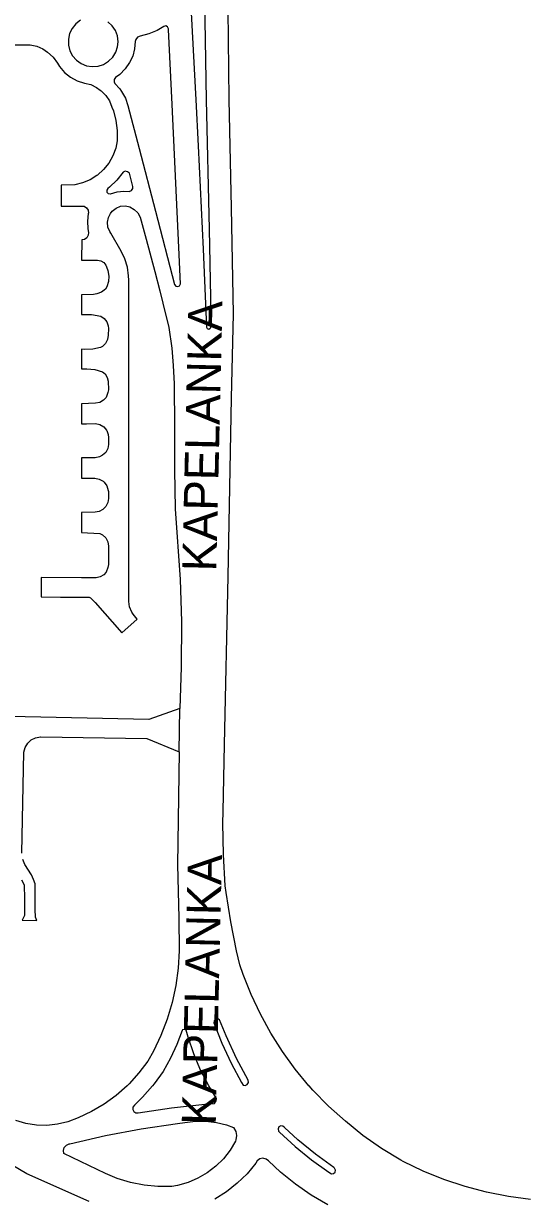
# Model space of a CAD drawing. Extents: x -304109 to -273954, y 21500 to 39796.
# Drawn here: x -294638.1 to -294489.1, y 28427.2 to 28772.6 of the extents above; entities that cross this region are included whole.
import ezdxf

# ---------------------------------------------------------------- set-up
doc = ezdxf.new("R2010")
doc.units = 0
doc.layers.add('krawedzie_ulic', color=7, linetype='Continuous')
doc.layers.add('nazwy_ulic', color=7, linetype='Continuous')

msp = doc.modelspace()

# ---------------------------------------------------------------- linework, layer by layer
at = {"layer": 'krawedzie_ulic'}
for points in [[(-294584.373, 28750.14), (-294583.568, 28712.137), (-294583.142, 28692.054), (-294583.142, 28683.142), (-294583.233, 28682.877), (-294583.62, 28682.645), (-294584.048, 28682.791), (-294584.211, 28683.213), (-294585.209, 28706.243), (-294586.706, 28736.585), (-294587.346, 28750.11), (-294589.288, 28786.733)], [(-294585.015, 28785.266), (-294584.373, 28750.14)], [(-294489.091, 28426.892), (-294495.579, 28427.789), (-294502.001, 28429.081), (-294508.333, 28430.762), (-294514.549, 28432.826), (-294520.629, 28435.266), (-294526.548, 28438.072), (-294527.25, 28438.435), (-294532.898, 28441.928), (-294538.325, 28445.755), (-294543.512, 28449.901), (-294548.441, 28454.352), (-294553.092, 28459.092), (-294554.172, 28460.278), (-294554.22, 28460.333), (-294558.274, 28465.245), (-294562.011, 28470.402), (-294565.418, 28475.783), (-294568.48, 28481.367), (-294571.185, 28487.133), (-294573.523, 28493.057), (-294574.481, 28495.853), (-294575.482, 28500), (-294577.211, 28508.554), (-294578.546, 28517.177), (-294578.795, 28519.151), (-294579.346, 28528.309), (-294579.498, 28537.482), (-294579.452, 28540.927), (-294578.991, 28560.669), (-294577.915, 28609.987), (-294576.966, 28662.456), (-294576.367, 28687.225), (-294577.01, 28718.357), (-294577.654, 28750.174), (-294578.099, 28785.592)], [(-294621.367, 28773.49), (-294622.726, 28772.454), (-294623.808, 28771.132), (-294624.553, 28769.595), (-294624.923, 28767.927), (-294624.895, 28766.219), (-294624.473, 28764.564), (-294623.678, 28763.052), (-294622.555, 28761.765), (-294621.164, 28760.774), (-294619.581, 28760.132), (-294617.892, 28759.875), (-294616.189, 28760.015), (-294614.566, 28760.547), (-294613.11, 28761.44), (-294611.901, 28762.647), (-294611.004, 28764.101), (-294610.469, 28765.723), (-294610.32, 28767.19)], [(-294610.32, 28767.19), (-294610.52, 28768.887), (-294611.107, 28770.491), (-294612.05, 28771.915), (-294613.297, 28773.082)], [(-294603.77, 28768.86), (-294604.56, 28768.51), (-294605.112, 28767.845), (-294605.29, 28767.28), (-294605.46, 28765.102), (-294606.023, 28762.991), (-294606.93, 28761.07), (-294608.227, 28759.2), (-294609.831, 28757.585), (-294611.04, 28756.68), (-294611.445, 28756.104), (-294611.479, 28755.4), (-294611.28, 28754.96), (-294609.82, 28753.33), (-294609.283, 28752.597), (-294608.159, 28750.596), (-294607.4, 28748.43), (-294604.09, 28735.79), (-294599.3, 28717.36), (-294593.73, 28695.859), (-294593.727, 28695.851), (-294593.366, 28695.38), (-294592.791, 28695.234), (-294592.248, 28695.476), (-294591.972, 28696.001), (-294592.494, 28706.721), (-294594.44, 28748.709), (-294595.529, 28770.787), (-294595.527, 28771.01), (-294595.785, 28771.553), (-294596.321, 28771.824), (-294596.911, 28771.709), (-294598.851, 28770.527), (-294601.246, 28769.504), (-294603.77, 28768.86)], [(-294644.8, 28766.29), (-294636.11, 28766.31), (-294634.202, 28765.902), (-294632.417, 28765.115), (-294631.05, 28764.17), (-294629.438, 28762.679), (-294628.122, 28760.921), (-294627.55, 28759.88), (-294626.066, 28758.194), (-294624.307, 28756.798), (-294622.328, 28755.735), (-294620.193, 28755.04), (-294620.15, 28755.03), (-294618.35, 28754.584), (-294616.686, 28753.763), (-294615.57, 28752.92), (-294615.302, 28752.718), (-294613.914, 28751.38), (-294612.831, 28749.784), (-294612.1, 28748), (-294611.695, 28746.899), (-294610.932, 28744.021), (-294610.562, 28741.067), (-294610.59, 28738.09), (-294611.013, 28735.949), (-294611.85, 28733.655), (-294613.05, 28731.529), (-294614.58, 28729.627), (-294616.4, 28728), (-294616.55, 28727.884), (-294618.549, 28726.614), (-294620.733, 28725.697), (-294623.04, 28725.16), (-294627.03, 28725.02), (-294627.05, 28718.9), (-294621.17, 28718.91), (-294620.319, 28718.856), (-294619.584, 28718.424), (-294619.122, 28717.708), (-294619.032, 28716.86), (-294619.06, 28716.7), (-294619.343, 28714.437), (-294619.227, 28712.16), (-294619.05, 28711.17)], [(-294606.96, 28728.53), (-294607.502, 28729.007), (-294608.213, 28729.13), (-294608.86, 28728.88), (-294610.719, 28726.538), (-294612.873, 28724.464), (-294613.33, 28724.09), (-294613.655, 28723.593), (-294613.603, 28723.002), (-294613.195, 28722.57), (-294612.608, 28722.483), (-294612.5, 28722.51), (-294610.578, 28723.087), (-294608.58, 28723.271), (-294607.03, 28723.14), (-294606.392, 28723.474), (-294606.023, 28724.093), (-294605.99, 28724.61), (-294606.96, 28728.53)], [(-294607.15, 28602.69), (-294607.18, 28627.96), (-294607.15, 28671.928), (-294607.18, 28697.08), (-294607.204, 28698.371), (-294607.552, 28700.912), (-294608.29, 28703.368), (-294609.4, 28705.68), (-294612.42, 28710.92), (-294612.764, 28711.434), (-294613.288, 28712.73), (-294613.426, 28714.121), (-294613.166, 28715.495), (-294612.53, 28716.74), (-294612.003, 28717.389), (-294610.879, 28718.277), (-294609.554, 28718.821), (-294608.13, 28718.98), (-294606.844, 28718.643), (-294605.557, 28717.917), (-294604.51, 28716.874), (-294603.78, 28715.59), (-294602.02, 28709.17), (-294599.503, 28699.713), (-294598.077, 28693.963), (-294597.112, 28690.364), (-294595.376, 28683.162), (-294594.52, 28677.126), (-294594.093, 28672.041), (-294593.808, 28666.624), (-294593.713, 28653.792), (-294593.744, 28641.376), (-294593.527, 28629.896), (-294592.037, 28609.148), (-294591.704, 28596.823), (-294591.796, 28583.358), (-294592.126, 28571.239)], [(-294619.05, 28711.17), (-294619.085, 28710.32), (-294619.5, 28709.577), (-294620.206, 28709.101), (-294621.01, 28708.99), (-294621.04, 28702.95), (-294616.34, 28702.96)], [(-294616.34, 28702.96), (-294615.342, 28702.814), (-294614.477, 28702.294), (-294613.879, 28701.482), (-294613.72, 28701.04), (-294613.37, 28699.92), (-294613.056, 28698.332), (-294613.138, 28696.715), (-294613.614, 28695.167), (-294613.96, 28694.5), (-294615.16, 28693.61), (-294616.553, 28693.068), (-294617.56, 28692.92), (-294621.07, 28692.82), (-294621.06, 28687.06), (-294618.092, 28686.983), (-294615.39, 28686.56), (-294614.361, 28685.864), (-294613.604, 28684.878), (-294613.197, 28683.704), (-294613.14, 28682.93), (-294613.18, 28680.92), (-294613.382, 28679.672), (-294613.962, 28678.548), (-294614.862, 28677.659), (-294615.45, 28677.31), (-294617.746, 28676.827), (-294620.09, 28676.74), (-294621.05, 28676.82), (-294621.07, 28671.04), (-294619.46, 28671.101), (-294617.137, 28670.851), (-294614.89, 28670.21), (-294614.105, 28669.554), (-294613.484, 28668.557), (-294613.23, 28667.41), (-294613.16, 28664.88), (-294613.291, 28664.12), (-294613.84, 28662.68), (-294614.628, 28661.817), (-294615.704, 28661.202), (-294616.92, 28660.96), (-294621.066, 28660.768), (-294621.064, 28654.868), (-294619.64, 28654.91), (-294616.93, 28654.99), (-294615.662, 28654.681), (-294614.547, 28654.004), (-294613.687, 28653.023), (-294613.66, 28652.98), (-294613.201, 28651.796), (-294613.11, 28650.84), (-294613.13, 28648.83), (-294613.356, 28647.601), (-294613.957, 28646.504), (-294614.871, 28645.652), (-294615.81, 28645.19), (-294617.008, 28644.909), (-294617.55, 28644.91), (-294621.06, 28644.93), (-294621.05, 28638.904), (-294620.05, 28638.9), (-294617.152, 28638.88), (-294615.85, 28638.627), (-294614.681, 28638), (-294614.41, 28637.78), (-294613.615, 28636.638), (-294613.176, 28635.317), (-294613.13, 28635), (-294613.16, 28632.98), (-294613.337, 28631.736), (-294613.894, 28630.61), (-294614.775, 28629.713), (-294615.892, 28629.137), (-294617.03, 28628.94), (-294621.07, 28628.85), (-294621.07, 28622.96), (-294615.64, 28622.66), (-294614.867, 28622.234), (-294613.942, 28621.343), (-294613.333, 28620.213), (-294613.1, 28618.95), (-294613.15, 28613.53), (-294613.298, 28612.645), (-294613.85, 28611.26), (-294614.491, 28610.547), (-294615.549, 28609.89), (-294616.76, 28609.6), (-294621.06, 28609.65), (-294632.93, 28609.69), (-294632.95, 28604), (-294627.2, 28603.97), (-294618.81, 28603.98), (-294618.459, 28603.794), (-294617.05, 28602.42)], [(-294617.05, 28602.42), (-294609.21, 28593.44), (-294604.69, 28597.49), (-294605.91, 28598.97), (-294606.291, 28599.568), (-294606.912, 28601.076), (-294607.15, 28602.69)], [(-294592.126, 28571.239), (-294601.281, 28568.04), (-294642.084, 28568.91)], [(-294592.335, 28558.511), (-294592.126, 28571.239)], [(-294638.6, 28528.738), (-294637.985, 28558.415), (-294637.612, 28559.791), (-294636.873, 28561.01), (-294635.826, 28561.978), (-294634.552, 28562.618), (-294633.151, 28562.881), (-294632.977, 28562.886), (-294601.815, 28562.425), (-294592.335, 28558.511)], [(-294592.335, 28558.511), (-294592.849, 28525.251), (-294592.496, 28509.676), (-294592.33, 28500), (-294592.621, 28494.886), (-294593.31, 28489.81), (-294594.393, 28484.804), (-294595.863, 28479.897), (-294597.712, 28475.119), (-294599.927, 28470.501), (-294601.577, 28467.565), (-294604.169, 28464.12), (-294607.068, 28460.931), (-294607.676, 28460.333), (-294610.911, 28457.484), (-294614.396, 28454.948), (-294618.102, 28452.745), (-294621.995, 28450.895), (-294625.081, 28449.728), (-294628.112, 28449.009), (-294631.21, 28448.684), (-294634.325, 28448.758), (-294637.404, 28449.23), (-294640.397, 28450.092)], [(-294638.704, 28520.907), (-294637.938, 28519.445), (-294637.859, 28515.314), (-294637.819, 28510.356), (-294638.469, 28509.027), (-294634.203, 28508.902), (-294634.573, 28509.896), (-294634.667, 28512.141), (-294634.707, 28515.554), (-294634.668, 28518.235), (-294634.708, 28519.711), (-294635.158, 28520.966), (-294635.727, 28522.329), (-294637.674, 28525.423), (-294638.335, 28526.812)], [(-294582.157, 28478.841), (-294579.811, 28472.838), (-294577.098, 28466.993), (-294574.027, 28461.327), (-294573.566, 28460.544), (-294572.916, 28460.461), (-294572.334, 28460.762), (-294572.026, 28461.342), (-294572.093, 28461.968), (-294575.497, 28468.405), (-294578.543, 28475.019), (-294580.453, 28479.732), (-294581.015, 28480.011), (-294581.634, 28479.905), (-294582.07, 28479.453), (-294582.157, 28478.841)], [(-294605.52, 28454.648), (-294605.942, 28454.088), (-294605.997, 28453.388), (-294605.668, 28452.769), (-294605.058, 28452.422), (-294604.421, 28452.437), (-294594.639, 28453.889), (-294584.806, 28454.945), (-294581.979, 28455.174), (-294581.508, 28455.901), (-294581.397, 28456.623), (-294583.67, 28460.333), (-294586.053, 28464.926), (-294588.075, 28469.69), (-294589.722, 28474.596), (-294590.296, 28476.674), (-294590.816, 28476.902), (-294591.36, 28476.743), (-294591.492, 28476.623), (-294592.999, 28472.443), (-294594.876, 28468.415), (-294597.107, 28464.573), (-294599.674, 28460.946), (-294600.159, 28460.333), (-294603.095, 28456.998), (-294605.52, 28454.648)], [(-294575.771, 28444.094), (-294577.393, 28441.378), (-294579.345, 28438.888), (-294581.595, 28436.665), (-294584.107, 28434.742), (-294586.842, 28433.152), (-294589.755, 28431.919), (-294592.8, 28431.063), (-294594.5, 28430.76), (-294598.595, 28430.759), (-294602.671, 28431.158), (-294606.688, 28431.952), (-294610.608, 28433.134), (-294614.054, 28434.534), (-294626.283, 28440.397), (-294626.4, 28441.325), (-294626.123, 28442.219), (-294625.502, 28442.918), (-294624.647, 28443.298), (-294624.508, 28443.322), (-294614.043, 28445.688), (-294603.497, 28447.662), (-294592.885, 28449.242), (-294590.646, 28449.524), (-294587.585, 28449.947), (-294584.495, 28449.971), (-294581.427, 28449.596), (-294578.434, 28448.829), (-294576.339, 28448.034), (-294575.729, 28446.927), (-294575.494, 28445.685), (-294575.655, 28444.432), (-294575.771, 28444.094)], [(-294562.822, 28446.747), (-294558.259, 28442.51), (-294553.434, 28438.575), (-294548.366, 28434.958), (-294547.602, 28434.454), (-294546.981, 28434.529), (-294546.525, 28434.958), (-294546.412, 28435.573), (-294546.686, 28436.136), (-294546.868, 28436.285), (-294552.279, 28440.218), (-294557.444, 28444.468), (-294561.4, 28448.096), (-294561.871, 28448.508), (-294562.495, 28448.562), (-294563.029, 28448.235), (-294563.267, 28447.656), (-294563.116, 28447.049), (-294562.822, 28446.747)], [(-294618.829, 28426.368), (-294637.138, 28434.492), (-294641.42, 28436.976)], [(-294569.802, 28437.565), (-294572.409, 28434.493), (-294575.308, 28431.695), (-294578.47, 28429.198), (-294581.864, 28427.027)], [(-294548.701, 28425.36), (-294553.539, 28428.238), (-294558.16, 28431.452), (-294562.541, 28434.985), (-294566.087, 28438.254), (-294566.824, 28438.818), (-294567.729, 28439.023), (-294568.637, 28438.833), (-294569.383, 28438.282), (-294569.802, 28437.565)]]:
    msp.add_lwpolyline(points, dxfattribs=at)

# ---------------------------------------------------------------- texts
at = {"layer": 'nazwy_ulic'}
for p in [(-294581.461, 28611.45), (-294581.618, 28448.709)]:
    msp.add_text('KAPELANKA', height=10, rotation=88.67449, dxfattribs=at).set_placement(p)

doc.saveas('drawing.dxf')
